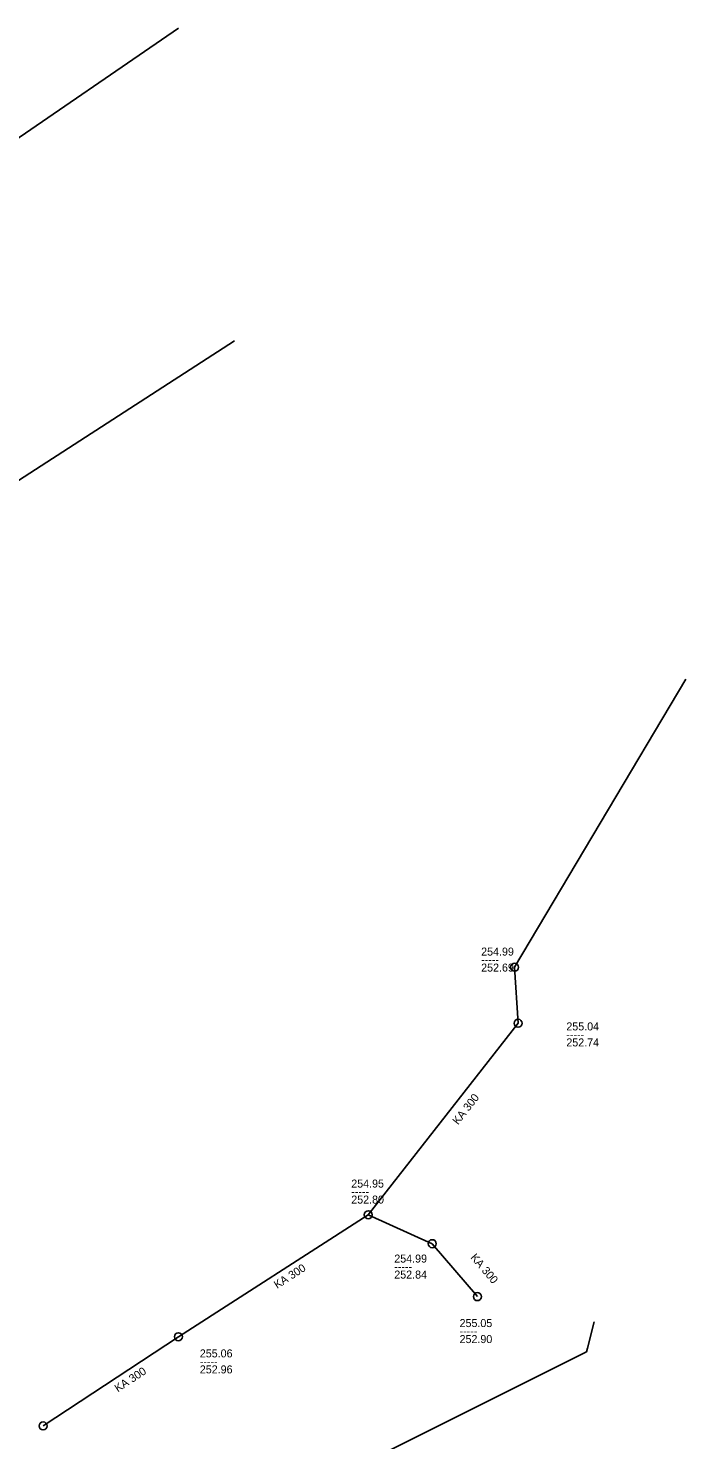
# Model space of a CAD drawing. Extents: x -647357 to -646700, y -1072205 to -1071664.
# Drawn here: x -646977 to -646894.8, y -1071963.6 to -1071787.3 of the extents above; entities that cross this region are included whole.
import ezdxf

# ---------------------------------------------------------------- set-up
doc = ezdxf.new("R2010")
doc.units = 0
for name, color, linetype in [('Level 19', 7, 'Continuous'), ('Level 20', 7, 'Continuous'), ('Level 40', 7, 'Continuous'), ('Level 41', 7, 'Continuous'), ('Level 44', 7, 'Continuous')]:
    doc.layers.add(name, color=color, linetype=linetype)

msp = doc.modelspace()

# ---------------------------------------------------------------- linework, layer by layer
at = {"layer": 'Level 19'}
msp.add_line((-646907.06, -1071952.18), (-646906.22, -1071948.89), dxfattribs=at)
at = {"layer": 'Level 20'}
for p, q in [((-647000.79, -1071816.43), (-646958.2, -1071787.26)), ((-646907.06, -1071952.18), (-646907.17, -1071952.67)), ((-646946.17, -1071972.11), (-646907.17, -1071952.67))]:
    msp.add_line(p, q, dxfattribs=at)
at = {"layer": 'Level 40'}
for p, q in [((-647003.4, -1071860.04), (-646951.17, -1071826.32)), ((-646916.17, -1071904.6), (-646894.77, -1071868.62)), ((-646915.73, -1071911.6), (-646916.17, -1071904.6)), ((-646934.46, -1071935.53), (-646915.73, -1071911.6)), ((-646958.2, -1071950.77), (-646934.46, -1071935.53)), ((-646926.47, -1071939.14), (-646934.46, -1071935.53)), ((-646920.82, -1071945.76), (-646926.47, -1071939.14)), ((-646975.11, -1071961.91), (-646958.2, -1071950.77))]:
    msp.add_line(p, q, dxfattribs=at)
at = {"layer": 'Level 41'}
for centre in [(-646916.17, -1071904.6), (-646915.73, -1071911.6), (-646934.46, -1071935.53), (-646926.47, -1071939.14), (-646920.82, -1071945.76), (-646958.2, -1071950.77), (-646975.11, -1071961.91)]:
    msp.add_circle(centre, 0.5, dxfattribs=at)

# ---------------------------------------------------------------- texts
at = {"layer": 'Level 44'}
for s, p in [('254.99', (-646920.35, -1071903.14)), ('-----', (-646920.35, -1071904.14)), ('252.69', (-646920.35, -1071905.14)), ('255.04', (-646909.7, -1071912.49)), ('-----', (-646909.7, -1071913.49)), ('252.74', (-646909.7, -1071914.49)), ('254.95', (-646936.59, -1071932.13)), ('-----', (-646936.59, -1071933.13)), ('252.80', (-646936.59, -1071934.13)), ('254.99', (-646931.21, -1071941.5)), ('-----', (-646931.21, -1071942.5)), ('252.84', (-646931.21, -1071943.5)), ('255.05', (-646923.05, -1071949.56)), ('-----', (-646923.05, -1071950.56)), ('252.90', (-646923.05, -1071951.56)), ('255.06', (-646955.52, -1071953.35)), ('-----', (-646955.52, -1071954.35)), ('252.96', (-646955.52, -1071955.35))]:
    msp.add_text(s, height=1, dxfattribs=at).set_placement(p)
for rotation, p in [(51.95, (-646923.24, -1071924.35)), (32.699, (-646945.86, -1071944.8)), (310.48, (-646921.75, -1071940.9)), (33.376, (-646965.77, -1071957.73))]:
    msp.add_text('KA 300', height=1, rotation=rotation, dxfattribs=at).set_placement(p)

doc.saveas('drawing.dxf')
